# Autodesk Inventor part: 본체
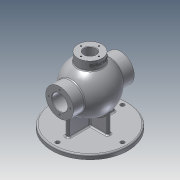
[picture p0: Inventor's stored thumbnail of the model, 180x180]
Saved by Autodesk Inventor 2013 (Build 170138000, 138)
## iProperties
Created: 2020-08
Part Number: 본체
Material: 알루미늄 6061
Document SubType Name: Modeling
Designer: user
Density: 2.71 g/cm^3
Mass: 1759.19 g
Surface Area: 1342.58 cm^2
Volume: 649.147 cm^3
Author: user
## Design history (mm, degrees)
sketch "스케치1"
  geometry: L1 (0, 53)-(0, -53); A1 r 53 centre (0, 0) between (0, -53) and (0, 53); 2 further points
  constraints: 2 end point, 2 point on circle, 2 vertical alignment, 1 centre point, 1 coincident, 1 midpoint, 1 vertical
  dimensions: "d81" = 53 radius of A1
revolve "회전1" sketch "스케치1" stored, may be unused: angle "d4" = 90 deg
node "작업 평면1"
sketch "스케치3"
  geometry: C1 r 31 at (0, 0); 1 further point
  constraints: 1 centre point, 1 coincident
  dimensions: "d9" = 62 diameter of C1
extrude "돌출1" join sketch "스케치3" distance "d10" = 136; taper "d11" = 0 deg
sketch "스케치2"
  geometry: L1 (0, 43)-(0, -43); A1 r 43 centre (0, 0) between (0, -43) and (0, 43); 2 further points
  constraints: 2 end point, 2 point on circle, 1 centre point, 1 coincident, 1 midpoint, 1 vertical alignment
  dimensions: "d5" = 43 radius of A1; "d6" = 86 distance of L1.start L1.end
revolve "회전2" sketch "스케치2" stored, may be unused: angle "d7" = 90 deg
node "작업 평면2"
sketch "스케치5"
  geometry: C1 r 27 at (0, 0); 1 further point
  constraints: 1 centre point, 1 coincident
  dimensions: "d20" = 54 diameter of C1
extrude "돌출2" join sketch "스케치5" stored distance "d21" = 136; taper "d22" = 0 deg
sketch "스케치6"
  geometry: C1 r 27 at (0, 0) reference; C2 r 13 at (0, 0)
  constraints: 1 centre point, 1 coincident
  dimensions: "d23" = 26 diameter of C2
extrude "돌출3" cut sketch "스케치6" stored distance "d24" = 136; taper "d25" = 0 deg
node "작업 평면3"
sketch "스케치7"
  geometry: C1 r 85 at (0, 0); 1 further point
  constraints: 1 centre point, 1 coincident
  dimensions: "d27" = 170 diameter of C1
extrude "돌출4" join sketch "스케치7" distance "d28" = 10; taper "d29" = 0 deg
sketch "스케치8"
  geometry: L1 (-52, 4)-(52, 4); L2 (52, 4)-(52, -4); L3 (52, -4)-(-52, -4); L4 (-52, -4)-(-52, 4); L5 (-4, 43)-(4, 43); L6 (4, 43)-(4, -43); L7 (4, -43)-(-4, -43); L8 (-4, -43)-(-4, 43); L9 (-52, 0)-(52, 0); L10 (0, 43)-(0, -43); C1 r 85 at (0, 0) reference; 1 further point
  constraints: 20 end point, 6 midpoint, 4 parallel, 2 horizontal, 2 perpendicular, 1 coincident
  dimensions: "d30" = 8 distance of L5.start L5.end; "d32" = 8 distance of L3.end L1.start; "d33" = 104 distance of L1.start L1.end; "d34" = 86 distance of L5.end L6.end
extrude "돌출5" join sketch "스케치8" stored distance "d35" = 10; taper "d36" = 0 deg
sketch "스케치4"
  geometry: L1 (-68, -31)-(-68, 31) reference; L2 (-68, 31)-(-42.988, 31) reference; L3 (42.988, 31)-(68, 31) reference; L4 (68, 31)-(68, -31) reference; L5 (68, -31)-(42.988, -31) reference; L6 (-42.988, -31)-(-68, -31) reference; L7 (-68, 0)-(68, 0); L8 (-68, 0)-(-68, 17.5); L9 (-68, 17.5)-(-52, 17.5); L10 (-52, 17.5)-(-52, 18.5); L11 (-52, 18.5)-(-50.25, 18.5); L12 (-50.25, 18.5)-(-50.25, 17.5); L13 (-50.25, 17.5)-(68, 17.5); L14 (68, 17.5)-(68, 0); C1 r 43 at (0, 0) reference; A1 r 53 centre (0, 0) between (42.988, 31) and (-42.988, 31) reference; A2 r 53 centre (0, 0) between (-42.988, -31) and (42.988, -31) reference; 1 further point
  constraints: 16 end point, 3 perpendicular, 2 midpoint, 2 parallel, 2 point on line, 1 collinear
  dimensions: "d12" = 35 diameter of L9 L7; "d14" = 16 distance of L8.end L9.end; "d15" = 37 diameter of L11 L7; "d16" = 1.75 distance of L10.end L11.end; "d17" = 35 diameter of L13 L7
revolve "회전3" sketch "스케치4" stored, may be unused: angle "d18" = 90 deg
node "작업 평면4"
sketch "스케치9"
  geometry: L1 (27, -65)-(27, -45.607) reference; L2 (27, -65)-(-27, -65) reference; 2 further points
  constraints: 1 other
  dimensions: "d38" = 9 distance from line of L2 point (0, -56); "d39" = 27 distance from line of L1 point (0, -56)
feature "엠보싱1" sketch "스케치9" dims "d12" = 35, "d14" = 16, "d15" = 37, "d16" = 1.75, "d17" = 35, "d40" = 0.5, "d41" = 0
sketch "스케치10" dims "d42" = 48
  geometry: C1 r 17.5 at (0, 0) reference; C2 r 31 at (0, 0) reference; 2 further points
  constraints: 2 vertical alignment, 1 coincident, 2 other
hole "구멍1" sketch "스케치10" at (0, 24) diameter "d43" = 3.242; stored, may be unused: countersink angle "d47" = 90 deg, drill point angle "d49" = 118 deg; dims "d44" = 12, "d45" = 4, "d46" = 2, "d48" = 15
sketch "스케치11" dims "d53" = 40
  geometry: C1 r 13 at (0, 0) reference; C2 r 27 at (0, 0) reference; 2 further points
  constraints: 2 vertical alignment, 1 coincident, 2 other
hole "구멍2" sketch "스케치11" at (0, 20) diameter "d54" = 3.242; stored, may be unused: countersink angle "d58" = 90 deg, drill point angle "d60" = 118 deg; dims "d55" = 12, "d56" = 4, "d57" = 2, "d59" = 15
sketch "스케치12" dims "d64" = 145
  geometry: C1 r 85 at (0, 0) reference; 2 further points
  constraints: 2 vertical alignment, 1 coincident, 2 other
hole "구멍3" sketch "스케치12" at (0, 72.5) diameter "d65" = 9; stored, may be unused: countersink angle "d69" = 90 deg, drill point angle "d71" = 118 deg; dims "d66" = 12, "d67" = 4, "d68" = 2, "d70" = 15
chamfer "모따기1" distance "d75" = 1; stored, may be unused: second distance "d76" = 2, angle "d77" = 45 deg
fillet "모깎기1" dims "d78" = 3
fillet "모깎기2" dims "d79" = 3
fillet "모깎기3" dims "d80" = 3
node "솔리드1"
pattern_circular "원형 패턴1" dims angle "d51" = 360 deg
mirror "대칭1"
pattern_circular "원형 패턴2" dims angle "d62" = 360 deg
pattern_circular "원형 패턴3" dims angle "d73" = 360 deg
node "절단 모서리 투영1"
other parameters: "d8" = 68, "d19" = -65, "d26" = 85, "d37" = -28
